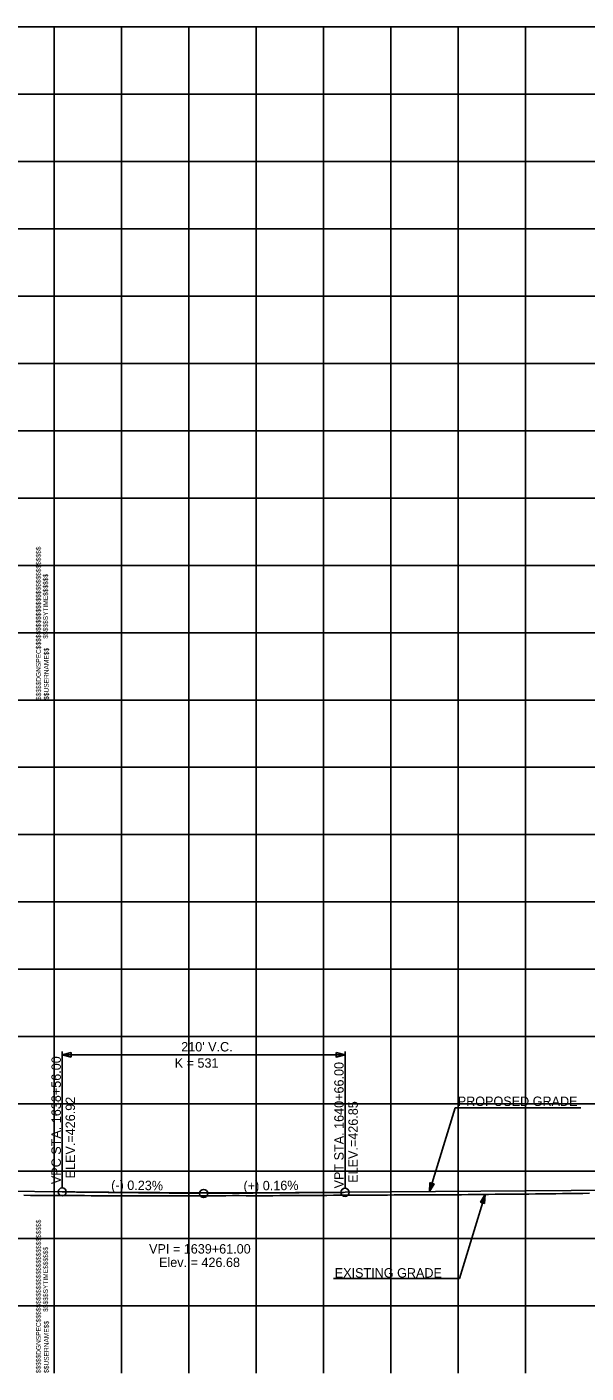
# Model space of a CAD drawing. Extents: x -90830 to 2015517, y -20856 to 836331.
# Drawn here: x 52753 to 53168, y -9797 to -8797 of the extents above; entities that cross this region are included whole.
import ezdxf

# ---------------------------------------------------------------- set-up
doc = ezdxf.new("R2010")
doc.units = 0
for name, color, linetype in [('Level 1', 7, 'Continuous'), ('RD_DDB_GradeTX', 7, 'Continuous'), ('RD_DDB_Profile_EX', 7, 'Continuous'), ('RD_DDB_Profile_Lbl', 7, 'Continuous'), ('RD_DDB_Profile_PR', 7, 'Continuous'), ('RD_DDB_StripGrade', 7, 'Continuous'), ('RD_DDB_VCLbl', 7, 'Continuous'), ('RD_PD_Final_TX', 7, 'Continuous')]:
    doc.layers.add(name, color=color, linetype=linetype)

msp = doc.modelspace()

# ---------------------------------------------------------------- linework, layer by layer
at = {"layer": 'Level 1'}
for p, q in [((51173.46, -8797.12), (52773.46, -8797.12)), ((52773.46, -8797.12), (52773.46, -9297.12)), ((52773.46, -8797.12), (52773.46, -9297.12)), ((52773.46, -8797.12), (54373.46, -8797.12)), ((52773.46, -8797.12), (52773.46, -9297.12)), ((52823.46, -8797.12), (52823.46, -9297.12)), ((52873.46, -8797.12), (52873.46, -9297.12)), ((52923.46, -8797.12), (52923.46, -9297.12)), ((52973.46, -8797.12), (52973.46, -9297.12)), ((53023.46, -8797.12), (53023.46, -9297.12)), ((53073.46, -8797.12), (53073.46, -9297.12)), ((53123.46, -8797.12), (53123.46, -9297.12)), ((51173.46, -8847.12), (52773.46, -8847.12)), ((52773.46, -8847.12), (54373.46, -8847.12)), ((51173.46, -8897.12), (52773.46, -8897.12)), ((52773.46, -8897.12), (54373.46, -8897.12)), ((51173.46, -8947.12), (52773.46, -8947.12)), ((52773.46, -8947.12), (54373.46, -8947.12)), ((51173.46, -8997.12), (52773.46, -8997.12)), ((52773.46, -8997.12), (54373.46, -8997.12)), ((51173.46, -9047.12), (52773.46, -9047.12)), ((52773.46, -9047.12), (54373.46, -9047.12)), ((51173.46, -9097.12), (52773.46, -9097.12)), ((52773.46, -9097.12), (54373.46, -9097.12)), ((51173.46, -9147.12), (52773.46, -9147.12)), ((52773.46, -9147.12), (54373.46, -9147.12)), ((51173.46, -9197.12), (52773.46, -9197.12)), ((52773.46, -9197.12), (54373.46, -9197.12)), ((51173.46, -9247.12), (52773.46, -9247.12)), ((52773.46, -9247.12), (54373.46, -9247.12)), ((51173.46, -9297.12), (52773.46, -9297.12)), ((51173.46, -9297.12), (52773.46, -9297.12)), ((52773.46, -9297.12), (52773.46, -9797.12)), ((52773.46, -9297.12), (52773.46, -9797.12)), ((52773.46, -9297.12), (54373.46, -9297.12)), ((52773.46, -9297.12), (54373.46, -9297.12)), ((52773.46, -9297.12), (52773.46, -9797.12)), ((52823.46, -9297.12), (52823.46, -9797.12)), ((52873.46, -9297.12), (52873.46, -9797.12)), ((52923.46, -9297.12), (52923.46, -9797.12)), ((52973.46, -9297.12), (52973.46, -9797.12)), ((53023.46, -9297.12), (53023.46, -9797.12)), ((53073.46, -9297.12), (53073.46, -9797.12)), ((53123.46, -9297.12), (53123.46, -9797.12)), ((51173.46, -9347.12), (52773.46, -9347.12)), ((52773.46, -9347.12), (54373.46, -9347.12)), ((51173.46, -9397.12), (52773.46, -9397.12)), ((52773.46, -9397.12), (54373.46, -9397.12)), ((51173.46, -9447.12), (52773.46, -9447.12)), ((52773.46, -9447.12), (54373.46, -9447.12)), ((51173.46, -9497.12), (52773.46, -9497.12)), ((52773.46, -9497.12), (54373.46, -9497.12)), ((51173.46, -9547.12), (52773.46, -9547.12)), ((52773.46, -9547.12), (54373.46, -9547.12)), ((51173.46, -9597.12), (52773.46, -9597.12)), ((52773.46, -9597.12), (54373.46, -9597.12)), ((51173.46, -9647.12), (52773.46, -9647.12)), ((52773.46, -9647.12), (54373.46, -9647.12)), ((51173.46, -9697.12), (52773.46, -9697.12)), ((52773.46, -9697.12), (54373.46, -9697.12)), ((51173.46, -9747.12), (52773.46, -9747.12)), ((52773.46, -9747.12), (54373.46, -9747.12))]:
    msp.add_line(p, q, dxfattribs=at)
at = {"layer": 'RD_DDB_GradeTX'}
for p, q in [((52813.46, -9662.89), (52881.46, -9663.68)), ((52955.46, -9663.13), (52887.46, -9663.69))]:
    msp.add_line(p, q, dxfattribs=at)
msp.add_circle((52884.46, -9663.71), 3, dxfattribs=at)
at = {"layer": 'RD_DDB_Profile_EX'}
for points in [[(52750.95, -9665.07), (52755.95, -9665.11), (52760.95, -9665.16), (52765.95, -9665.2), (52770.95, -9665.23), (52775.95, -9665.23), (52780.95, -9665.24), (52785.95, -9665.25), (52790.95, -9665.27), (52795.95, -9665.31), (52800.95, -9665.35), (52805.95, -9665.39), (52810.95, -9665.42), (52815.95, -9665.44), (52820.95, -9665.46), (52825.95, -9665.48), (52830.95, -9665.5), (52835.95, -9665.52), (52840.95, -9665.54), (52845.95, -9665.56), (52850.95, -9665.57), (52855.95, -9665.55), (52860.95, -9665.54), (52865.95, -9665.52), (52870.95, -9665.49), (52875.95, -9665.45), (52880.95, -9665.4), (52885.95, -9665.37), (52890.95, -9665.34), (52895.95, -9665.34), (52900.95, -9665.33), (52905.95, -9665.32), (52910.95, -9665.32), (52915.95, -9665.34), (52920.95, -9665.35)], [(52920.95, -9665.35), (52925.95, -9665.38), (52930.95, -9665.37), (52935.95, -9665.33), (52940.95, -9665.28), (52945.95, -9665.23), (52950.95, -9665.2), (52955.95, -9665.2), (52960.95, -9665.21), (52965.95, -9665.2), (52970.95, -9665.18), (52975.95, -9665.11), (52980.95, -9665.06), (52985.95, -9665), (52990.95, -9664.97), (52995.95, -9664.96), (53000.95, -9664.95), (53005.95, -9664.95), (53010.95, -9664.93), (53015.95, -9664.88), (53020.95, -9664.84), (53025.95, -9664.81), (53030.95, -9664.78), (53035.95, -9664.75), (53040.95, -9664.73), (53045.95, -9664.7), (53050.95, -9664.69), (53055.95, -9664.69), (53060.95, -9664.69), (53065.95, -9664.7), (53070.95, -9664.67), (53075.95, -9664.6), (53080.95, -9664.53), (53085.95, -9664.46), (53090.95, -9664.41), (53095.95, -9664.37), (53100.95, -9664.33), (53105.95, -9664.3), (53110.95, -9664.26), (53115.95, -9664.21), (53120.95, -9664.16), (53125.95, -9664.11), (53130.95, -9664.05), (53135.95, -9664), (53140.95, -9663.94), (53145.95, -9663.88), (53150.95, -9663.83), (53155.95, -9663.77), (53160.95, -9663.71), (53165.95, -9663.65), (53170.95, -9663.58)]]:
    msp.add_lwpolyline(points, dxfattribs=at)
at = {"layer": 'RD_DDB_Profile_PR'}
for p, q in [((52738.46, -9662.03), (52779.46, -9662.5)), ((52989.46, -9662.85), (53213.46, -9661.02))]:
    msp.add_line(p, q, dxfattribs=at)
msp.add_spline([(52779.46, -9662.5), (52783.66, -9662.55), (52787.86, -9662.59), (52792.06, -9662.64), (52796.26, -9662.68), (52800.46, -9662.72), (52804.66, -9662.76), (52808.86, -9662.8), (52813.06, -9662.84), (52817.26, -9662.87), (52821.46, -9662.9), (52825.66, -9662.93), (52829.86, -9662.96), (52834.06, -9662.99), (52838.26, -9663.02), (52842.46, -9663.04), (52846.66, -9663.06), (52850.86, -9663.09), (52855.06, -9663.11), (52859.26, -9663.12), (52863.46, -9663.14), (52867.66, -9663.15), (52871.86, -9663.17), (52876.06, -9663.18), (52880.26, -9663.19), (52884.46, -9663.2), (52888.66, -9663.2), (52892.86, -9663.21), (52897.06, -9663.21), (52901.26, -9663.21), (52905.46, -9663.21), (52909.66, -9663.21), (52913.86, -9663.2), (52918.06, -9663.2), (52922.26, -9663.19), (52926.46, -9663.18), (52930.66, -9663.17), (52934.86, -9663.16), (52939.06, -9663.15), (52943.26, -9663.13), (52947.46, -9663.12), (52951.66, -9663.1), (52955.86, -9663.08), (52960.06, -9663.05), (52964.26, -9663.03), (52968.46, -9663.01), (52972.66, -9662.98), (52976.86, -9662.95), (52981.06, -9662.92), (52985.26, -9662.89), (52989.46, -9662.85)], degree=3, dxfattribs=at)
at = {"layer": 'RD_DDB_VCLbl'}
for p, q in [((52779.46, -9558.2), (52779.46, -9659.5)), ((52989.46, -9558.2), (52989.46, -9659.85)), ((52779.46, -9560.7), (52989.46, -9560.7))]:
    msp.add_line(p, q, dxfattribs=at)
for centre in [(52779.46, -9662.5), (52989.46, -9662.85)]:
    msp.add_circle(centre, 3, dxfattribs=at)
at = {"layer": 'RD_PD_Final_TX'}
for p, q in [((53052.16, -9662.34), (53071.21, -9599.97)), ((53071.21, -9599.97), (53164.6, -9599.97)), ((53052.16, -9662.34), (53052.5, -9655.67)), ((53054.05, -9656.14), (53052.16, -9662.34)), ((53052.16, -9662.34), (53055.6, -9656.62)), ((53052.5, -9655.67), (53055.6, -9656.62)), ((53093.45, -9664.39), (53090.01, -9670.11)), ((53091.56, -9670.59), (53093.45, -9664.39)), ((53093.45, -9664.39), (53093.11, -9671.06)), ((53093.11, -9671.06), (53090.01, -9670.11))]:
    msp.add_line(p, q, dxfattribs=at)
for points in [[(52786.06, -9562.35), (52779.46, -9560.7), (52786.06, -9559.05)], [(52982.86, -9559.05), (52989.46, -9560.7), (52982.86, -9562.35)]]:
    msp.add_lwpolyline(points, close=True, dxfattribs=at)
for points in [[(53053.98, -9656.21), (53052.22, -9661.98), (53053.95, -9656.16), (53052.25, -9661.69), (53053.88, -9656.16), (53052.25, -9661.5), (53053.8, -9656.15), (53052.26, -9661.26), (53053.74, -9656.12), (53052.28, -9660.9), (53053.66, -9656.08), (53052.31, -9660.52), (53053.57, -9656.08), (53052.33, -9660.23), (53053.51, -9656.05), (53052.35, -9659.9), (53053.43, -9656.07), (53052.37, -9659.61), (53053.39, -9656), (53052.37, -9659.36), (53053.29, -9655.99), (53052.38, -9659), (53053.22, -9655.96), (53052.43, -9658.56), (53053.14, -9655.92), (53052.41, -9658.26), (53053.07, -9655.9), (53052.44, -9657.81), (53052.98, -9655.9), (53052.48, -9657.44), (53052.9, -9655.83), (53052.49, -9657.13), (53052.83, -9655.84), (53052.5, -9656.83), (53052.77, -9655.78), (53052.52, -9656.48), (53052.69, -9655.81), (53052.55, -9656.08), (53052.6, -9655.81)], [(53052.32, -9661.95), (53054.07, -9656.23), (53052.43, -9661.76), (53054.15, -9656.26), (53052.52, -9661.58), (53054.21, -9656.25), (53052.64, -9661.42), (53054.25, -9656.28), (53052.77, -9661.22), (53054.32, -9656.28), (53052.89, -9661.03), (53054.37, -9656.3), (53053.02, -9660.81), (53054.44, -9656.3), (53053.18, -9660.53), (53054.53, -9656.35), (53053.31, -9660.29), (53054.59, -9656.34), (53053.45, -9660.04), (53054.65, -9656.37), (53053.61, -9659.81), (53054.71, -9656.39), (53053.76, -9659.55), (53054.75, -9656.44), (53053.96, -9659.2), (53054.82, -9656.44), (53054.11, -9658.98), (53054.88, -9656.43), (53054.3, -9658.69), (53054.94, -9656.47), (53054.45, -9658.38), (53055.01, -9656.51), (53054.59, -9658.15), (53055.08, -9656.57), (53054.76, -9657.93), (53055.13, -9656.58), (53054.94, -9657.58), (53055.23, -9656.56), (53055.05, -9657.37), (53055.34, -9656.59), (53055.18, -9657.24), (53055.42, -9656.69), (53055.5, -9656.64), (53055.39, -9656.68)], [(52981.01, -9726.76), (53074.4, -9726.76), (53093.45, -9664.39)], [(53093.28, -9664.78), (53091.54, -9670.5), (53093.18, -9664.97), (53091.46, -9670.47), (53093.08, -9665.15), (53091.4, -9670.48), (53092.96, -9665.31), (53091.35, -9670.45), (53092.83, -9665.51), (53091.28, -9670.45), (53092.72, -9665.7), (53091.23, -9670.43), (53092.58, -9665.92), (53091.16, -9670.42), (53092.43, -9666.2), (53091.08, -9670.38), (53092.3, -9666.44), (53091.02, -9670.39), (53092.15, -9666.69), (53090.96, -9670.36), (53092, -9666.92), (53090.9, -9670.34), (53091.85, -9667.18), (53090.86, -9670.29), (53091.64, -9667.53), (53090.78, -9670.29), (53091.49, -9667.75), (53090.72, -9670.3), (53091.3, -9668.04), (53090.67, -9670.26), (53091.15, -9668.35), (53090.6, -9670.22), (53091.01, -9668.58), (53090.53, -9670.16), (53090.85, -9668.8), (53090.48, -9670.14), (53090.67, -9669.15), (53090.37, -9670.17), (53090.55, -9669.35), (53090.27, -9670.14), (53090.43, -9669.48), (53090.19, -9670.04), (53090.1, -9670.09), (53090.21, -9670.05)], [(53091.62, -9670.52), (53093.39, -9664.75), (53091.65, -9670.57), (53093.36, -9665.04), (53091.72, -9670.57), (53093.35, -9665.23), (53091.8, -9670.58), (53093.35, -9665.47), (53091.86, -9670.61), (53093.33, -9665.83), (53091.95, -9670.65), (53093.29, -9666.21), (53092.04, -9670.65), (53093.27, -9666.5), (53092.1, -9670.68), (53093.26, -9666.83), (53092.17, -9670.66), (53093.24, -9667.12), (53092.22, -9670.73), (53093.23, -9667.37), (53092.32, -9670.73), (53093.22, -9667.73), (53092.39, -9670.77), (53093.17, -9668.16), (53092.46, -9670.81), (53093.19, -9668.46), (53092.54, -9670.83), (53093.17, -9668.92), (53092.62, -9670.83), (53093.12, -9669.28), (53092.7, -9670.89), (53093.11, -9669.6), (53092.77, -9670.89), (53093.11, -9669.9), (53092.84, -9670.95), (53093.08, -9670.25), (53092.92, -9670.92), (53093.06, -9670.65), (53093, -9670.92)]]:
    msp.add_lwpolyline(points, dxfattribs=at)

# ---------------------------------------------------------------- texts
at = {"layer": 'Level 1'}
for s, p in [('$$$$$DGNSPEC$$$$$$$$$$$$$$$$$$$$$$$$$$$$', (52763.56, -9297.17)), ('$$$$$SYTIME$$$$$$', (52768.86, -9251.57)), ('$$USERNAME$$', (52769.46, -9297.02)), ('$$$$$DGNSPEC$$$$$$$$$$$$$$$$$$$$$$$$$$$$', (52763.56, -9797.17)), ('$$$$$SYTIME$$$$$$', (52768.86, -9751.57)), ('$$USERNAME$$', (52769.46, -9797.02))]:
    msp.add_text(s, height=3.5436, rotation=90, dxfattribs=at).set_placement(p)
at = {"layer": 'RD_DDB_GradeTX'}
for s, rotation, p in [('(-) 0.23%', 359.33743, (52815.78, -9660.92)), ('(+) 0.16%', 0.46956, (52914.11, -9661.47))]:
    msp.add_text(s, height=7, rotation=rotation, dxfattribs=at).set_placement(p)
at = {"layer": 'RD_DDB_Profile_Lbl'}
for s, p in [('VPI = 1639+61.00', (52843.95, -9708.34)), ('Elev. = 426.68', (52851.36, -9718.34))]:
    msp.add_text(s, height=7, dxfattribs=at).set_placement(p)
at = {"layer": 'RD_DDB_StripGrade'}
for s, p in [('VPC STA. 1638+56.00 ', (52778.46, -9656.75)), ('VPT STA. 1640+66.00 ', (52988.46, -9659.94)), ('ELEV.=426.92', (52788.96, -9652.5)), ('ELEV.=426.85', (52998.96, -9655.78))]:
    msp.add_text(s, height=7, rotation=90, dxfattribs=at).set_placement(p)
at = {"layer": 'RD_DDB_VCLbl'}
for s, p in [("210' V.C.", (52867.82, -9558.22)), ('K = 531', (52862.98, -9570.28))]:
    msp.add_text(s, height=7, dxfattribs=at).set_placement(p)
at = {"layer": 'RD_PD_Final_TX'}
for s, p in [('PROPOSED GRADE', (53073.16, -9598.71)), ('EXISTING GRADE', (52981.83, -9726.16))]:
    msp.add_text(s, height=7, dxfattribs=at).set_placement(p)

doc.saveas('drawing.dxf')
